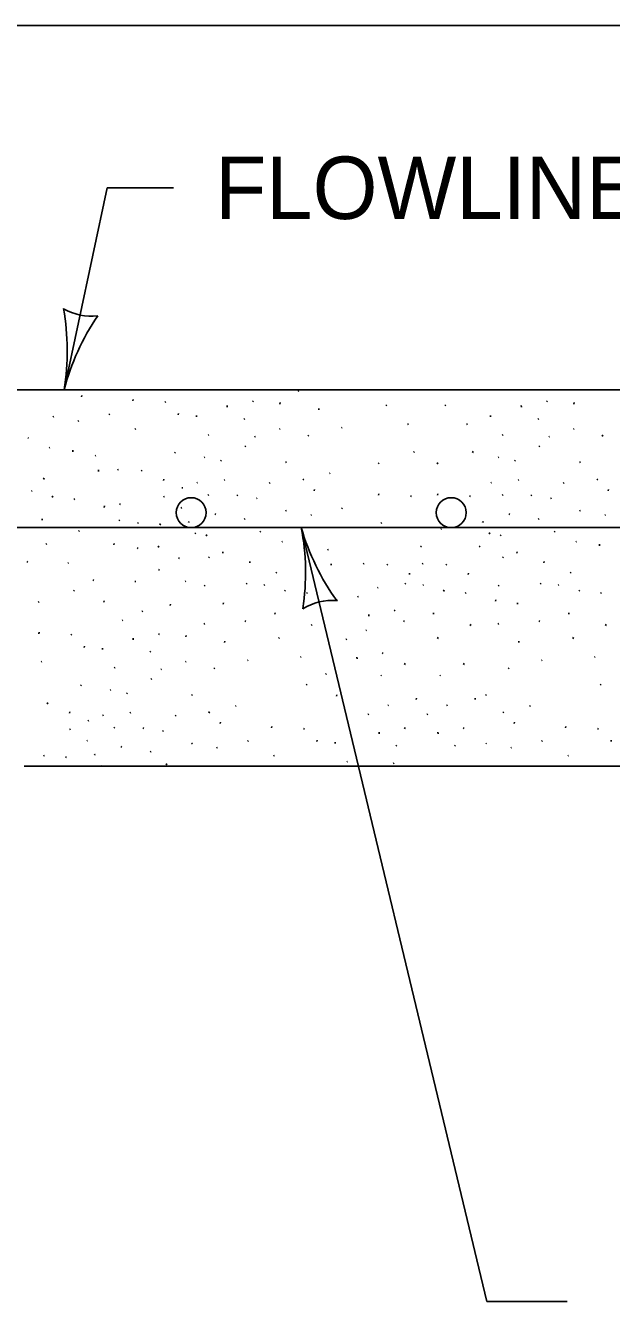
# Model space of a CAD drawing. Extents: x 49991.4 to 50029.7, y 49987.6 to 50011.4.
# Drawn here: x 50028.064 to 50028.627, y 49992.655 to 49993.881 of the extents above; entities that cross this region are included whole.
import ezdxf

# ---------------------------------------------------------------- set-up
doc = ezdxf.new("R2010")
doc.units = 0
for name, color, linetype in [('Level 1', 7, 'Continuous'), ('Level 2', 7, 'Continuous'), ('Level 3', 7, 'Continuous'), ('Level 4', 7, 'Continuous'), ('Level 5', 7, 'Continuous'), ('Level 9', 7, 'Continuous')]:
    doc.layers.add(name, color=color, linetype=linetype)

msp = doc.modelspace()

# ---------------------------------------------------------------- linework, layer by layer
at = {"layer": 'Level 1'}
for p, q in [((50028.0661, 49993.5314), (50029.3148, 49993.5314)), ((50028.0624, 49993.1696), (50029.3148, 49993.1696))]:
    msp.add_line(p, q, dxfattribs=at)
for centre in [(50028.223, 49993.4133), (50028.473, 49993.4133)]:
    msp.add_circle(centre, 0.0144, dxfattribs=at)
at = {"layer": 'Level 3'}
for p, q in [((50028.1421, 49993.7255), (50028.101, 49993.5314)), ((50028.1421, 49993.7255), (50028.2061, 49993.7255)), ((50028.3288, 49993.3989), (50028.5073, 49992.6553)), ((50028.5073, 49992.6553), (50028.5844, 49992.6553))]:
    msp.add_line(p, q, dxfattribs=at)
for centre, radius, start, end in [((50028.1276, 49993.6568), 0.0548, 240.156, 275.8784), ((50027.8709, 49993.5685), 0.233, 350.8445, 10.0944), ((50028.3163, 49993.4763), 0.2223, 145.4732, 165.6567), ((50028.1107, 49993.356), 0.2223, 350.9492, 11.1327), ((50028.5524, 49993.4644), 0.233, 196.3205, 215.5704), ((50028.3588, 49993.2742), 0.0548, 85.632, 121.3544)]:
    msp.add_arc(centre, radius, start, end, dxfattribs=at)
at = {"layer": 'Level 4'}
msp.add_line((50027.9165, 49993.3989), (50029.0416, 49993.3989), dxfattribs=at)
at = {"layer": 'Level 5'}
for p, q in [((50029.3148, 49993.8814), (50026.0794, 49993.8814)), ((50028.0661, 49993.5314), (50027.8717, 49993.5314))]:
    msp.add_line(p, q, dxfattribs=at)
at = {"layer": 'Level 9'}
for p, q in [((50028.3264, 49993.5303), (50028.3256, 49993.5299)), ((50028.1178, 49993.526), (50028.1176, 49993.5247)), ((50028.1671, 49993.5219), (50028.1669, 49993.5206)), ((50028.1986, 49993.5191), (50028.1976, 49993.52)), ((50028.2829, 49993.5198), (50028.2819, 49993.5206)), ((50028.3085, 49993.519), (50028.3082, 49993.5177)), ((50028.5656, 49993.5198), (50028.5646, 49993.5206)), ((50028.5911, 49993.519), (50028.5909, 49993.5177)), ((50028.0909, 49993.5057), (50028.0901, 49993.5053)), ((50028.1448, 49993.5074), (50028.1438, 49993.5083)), ((50028.2108, 49993.5086), (50028.2106, 49993.5073)), ((50028.2282, 49993.5066), (50028.228, 49993.5053)), ((50028.2576, 49993.5162), (50028.2577, 49993.5148)), ((50028.3458, 49993.5134), (50028.3456, 49993.5121)), ((50028.411, 49993.516), (50028.41, 49993.5168)), ((50028.4677, 49993.516), (50028.4667, 49993.5168)), ((50028.5109, 49993.5066), (50028.5107, 49993.5053)), ((50028.5403, 49993.5162), (50028.5404, 49993.5148)), ((50028.115, 49993.5016), (50028.1142, 49993.5012)), ((50028.1698, 49993.494), (50028.169, 49993.4936)), ((50028.2746, 49993.5029), (50028.2736, 49993.5038)), ((50028.3086, 49993.494), (50028.3078, 49993.4936)), ((50028.3682, 49993.4951), (50028.3674, 49993.4948)), ((50028.4319, 49993.4985), (50028.4311, 49993.4981)), ((50028.4886, 49993.4985), (50028.4877, 49993.4981)), ((50028.5573, 49993.5029), (50028.5563, 49993.5038)), ((50028.5913, 49993.494), (50028.5905, 49993.4936)), ((50028.0665, 49993.4849), (50028.0661, 49993.4852)), ((50028.2401, 49993.4881), (50028.2393, 49993.4877)), ((50028.2848, 49993.4866), (50028.284, 49993.4862)), ((50028.3362, 49993.4868), (50028.3352, 49993.4877)), ((50028.5228, 49993.4881), (50028.522, 49993.4877)), ((50028.5675, 49993.4866), (50028.5667, 49993.4862)), ((50028.6189, 49993.4868), (50028.6179, 49993.4877)), ((50028.0872, 49993.476), (50028.0864, 49993.4757)), ((50028.1091, 49993.4733), (50028.1092, 49993.4719)), ((50028.2079, 49993.4706), (50028.2069, 49993.4715)), ((50028.2755, 49993.4767), (50028.2745, 49993.4776)), ((50028.4376, 49993.4712), (50028.4366, 49993.4721)), ((50028.4943, 49993.4712), (50028.4932, 49993.4721)), ((50028.5582, 49993.4767), (50028.5572, 49993.4776)), ((50028.1314, 49993.4683), (50028.1306, 49993.468)), ((50028.2362, 49993.4666), (50028.2354, 49993.4663)), ((50028.2521, 49993.4629), (50028.2511, 49993.4637)), ((50028.3145, 49993.462), (50028.3137, 49993.4616)), ((50028.4037, 49993.4603), (50028.4027, 49993.4612)), ((50028.4603, 49993.4603), (50028.4593, 49993.4612)), ((50028.5189, 49993.4666), (50028.518, 49993.4663)), ((50028.5348, 49993.4629), (50028.5338, 49993.4637)), ((50028.5972, 49993.462), (50028.5964, 49993.4616)), ((50028.0819, 49993.4455), (50028.0808, 49993.4464)), ((50028.1339, 49993.4544), (50028.134, 49993.453)), ((50028.153, 49993.4548), (50028.1522, 49993.4545)), ((50028.1758, 49993.4533), (50028.1748, 49993.4542)), ((50028.1967, 49993.4456), (50028.1965, 49993.4443)), ((50028.2554, 49993.4449), (50028.2546, 49993.4445)), ((50028.3312, 49993.4448), (50028.3302, 49993.4456)), ((50028.3567, 49993.4512), (50028.3559, 49993.4509)), ((50028.5381, 49993.4449), (50028.5373, 49993.4445)), ((50028.6139, 49993.4448), (50028.6129, 49993.4456)), ((50028.0702, 49993.4342), (50028.0694, 49993.4338)), ((50028.2149, 49993.4373), (50028.214, 49993.437)), ((50028.2291, 49993.4424), (50028.2283, 49993.442)), ((50028.299, 49993.4414), (50028.298, 49993.4422)), ((50028.3415, 49993.4357), (50028.3412, 49993.4344)), ((50028.5118, 49993.4424), (50028.511, 49993.442)), ((50028.5817, 49993.4414), (50028.5807, 49993.4422)), ((50028.6242, 49993.4357), (50028.6239, 49993.4344)), ((50028.0902, 49993.4283), (50028.0892, 49993.4291)), ((50028.1111, 49993.4265), (50028.1103, 49993.4261)), ((50028.155, 49993.421), (50028.154, 49993.4219)), ((50028.1973, 49993.4288), (50028.1964, 49993.4285)), ((50028.2401, 49993.4299), (50028.2391, 49993.4308)), ((50028.2678, 49993.4294), (50028.2668, 49993.4303)), ((50028.2866, 49993.4272), (50028.2858, 49993.4269)), ((50028.4034, 49993.4315), (50028.4032, 49993.4302)), ((50028.4349, 49993.4288), (50028.4339, 49993.4296)), ((50028.4601, 49993.4315), (50028.4599, 49993.4302)), ((50028.4916, 49993.4288), (50028.4906, 49993.4296)), ((50028.5228, 49993.4299), (50028.5218, 49993.4308)), ((50028.5504, 49993.4294), (50028.5494, 49993.4303)), ((50028.5693, 49993.4272), (50028.5685, 49993.4269)), ((50028.1397, 49993.4197), (50028.1394, 49993.4184)), ((50028.2139, 49993.4181), (50028.213, 49993.4177)), ((50028.2467, 49993.4115), (50028.2457, 49993.4123)), ((50028.3145, 49993.4153), (50028.3137, 49993.415)), ((50028.3387, 49993.4112), (50028.3379, 49993.4109)), ((50028.3684, 49993.4171), (50028.3674, 49993.418)), ((50028.5294, 49993.4115), (50028.5284, 49993.4123)), ((50028.5972, 49993.4153), (50028.5964, 49993.415)), ((50028.6214, 49993.4112), (50028.6205, 49993.4109)), ((50028.0799, 49993.4073), (50028.0797, 49993.406)), ((50028.1158, 49993.3952), (50028.1148, 49993.3961)), ((50028.1545, 49993.4054), (50028.1535, 49993.4063)), ((50028.1723, 49993.4036), (50028.1715, 49993.4033)), ((50028.1937, 49993.4016), (50028.1927, 49993.4025)), ((50028.2204, 49993.404), (50028.2208, 49993.4044)), ((50028.2208, 49993.4044), (50028.2212, 49993.4045)), ((50028.2749, 49993.4074), (50028.274, 49993.407)), ((50028.2901, 49993.3945), (50028.2891, 49993.3954)), ((50028.4062, 49993.4036), (50028.4053, 49993.4033)), ((50028.4628, 49993.4036), (50028.462, 49993.4033)), ((50028.4637, 49993.3977), (50028.4629, 49993.3974)), ((50028.5031, 49993.404), (50028.5035, 49993.4044)), ((50028.5035, 49993.4044), (50028.5039, 49993.4045)), ((50028.5575, 49993.4074), (50028.5567, 49993.407)), ((50028.5728, 49993.3945), (50028.5718, 49993.3954)), ((50028.0844, 49993.3827), (50028.0834, 49993.3836)), ((50028.149, 49993.3838), (50028.1488, 49993.3825)), ((50028.2276, 49993.3929), (50028.2266, 49993.3938)), ((50028.2383, 49993.3911), (50028.2372, 49993.392)), ((50028.3108, 49993.3857), (50028.31, 49993.3853)), ((50028.5103, 49993.3929), (50028.5093, 49993.3938)), ((50028.5209, 49993.3911), (50028.5199, 49993.392)), ((50028.5935, 49993.3857), (50028.5927, 49993.3853)), ((50028.1721, 49993.3788), (50028.1711, 49993.3796)), ((50028.1921, 49993.3801), (50028.1911, 49993.381)), ((50028.2406, 49993.37), (50028.2396, 49993.3709)), ((50028.2536, 49993.3756), (50028.2534, 49993.3743)), ((50028.3327, 49993.3829), (50028.3328, 49993.3815)), ((50028.355, 49993.378), (50028.3542, 49993.3776)), ((50028.4443, 49993.3803), (50028.4433, 49993.3811)), ((50028.5009, 49993.3803), (50028.4999, 49993.3811)), ((50028.5233, 49993.37), (50028.5223, 49993.3709)), ((50028.5363, 49993.3756), (50028.5361, 49993.3743)), ((50028.6154, 49993.3829), (50028.6155, 49993.3815)), ((50028.0659, 49993.3656), (50028.0649, 49993.3664)), ((50028.1052, 49993.3652), (50028.1044, 49993.3649)), ((50028.1926, 49993.3579), (50028.1916, 49993.3587)), ((50028.2117, 49993.3691), (50028.2107, 49993.3699)), ((50028.2795, 49993.3664), (50028.2793, 49993.3651)), ((50028.3576, 49993.3641), (50028.3577, 49993.3627)), ((50028.3894, 49993.3645), (50028.3885, 49993.3641)), ((50028.4121, 49993.363), (50028.4111, 49993.3638)), ((50028.446, 49993.3645), (50028.4452, 49993.3641)), ((50028.4688, 49993.363), (50028.4678, 49993.3638)), ((50028.5622, 49993.3664), (50028.562, 49993.3651)), ((50028.1295, 49993.3481), (50028.1285, 49993.3489)), ((50028.1697, 49993.3473), (50028.1689, 49993.347)), ((50028.2179, 49993.3474), (50028.2171, 49993.3471)), ((50028.3055, 49993.3552), (50028.3045, 49993.356)), ((50028.433, 49993.3553), (50028.4328, 49993.354)), ((50028.4897, 49993.3553), (50028.4894, 49993.354)), ((50028.5882, 49993.3552), (50028.5872, 49993.356)), ((50028.1109, 49993.3379), (50028.1099, 49993.3388)), ((50028.2365, 49993.3427), (50028.2355, 49993.3435)), ((50028.2769, 49993.3446), (50028.2759, 49993.3455)), ((50028.2938, 49993.3438), (50028.293, 49993.3435)), ((50028.3138, 49993.3379), (50028.3128, 49993.3388)), ((50028.3347, 49993.3361), (50028.3339, 49993.3358)), ((50028.4028, 49993.3414), (50028.402, 49993.341)), ((50028.4295, 49993.3446), (50028.4285, 49993.3455)), ((50028.4464, 49993.3438), (50028.4456, 49993.3435)), ((50028.4664, 49993.3379), (50028.4654, 49993.3388)), ((50028.4873, 49993.3361), (50028.4865, 49993.3358)), ((50028.5192, 49993.3427), (50028.5182, 49993.3435)), ((50028.5596, 49993.3446), (50028.5586, 49993.3455)), ((50028.5765, 49993.3438), (50028.5757, 49993.3435)), ((50028.5965, 49993.3379), (50028.5955, 49993.3388)), ((50028.6174, 49993.3361), (50028.6166, 49993.3358)), ((50028.077, 49993.3271), (50028.076, 49993.3279)), ((50028.1393, 49993.3285), (50028.1391, 49993.3272)), ((50028.2032, 49993.3254), (50028.2029, 49993.3241)), ((50028.2541, 49993.3268), (50028.2539, 49993.3255)), ((50028.3633, 49993.3294), (50028.3631, 49993.3281)), ((50028.3838, 49993.3328), (50028.383, 49993.3324)), ((50028.5159, 49993.3294), (50028.5156, 49993.3281)), ((50028.5368, 49993.3268), (50028.5366, 49993.3255)), ((50028.1574, 49993.3101), (50028.1566, 49993.3098)), ((50028.1764, 49993.3187), (50028.1756, 49993.3184)), ((50028.2756, 49993.3086), (50028.2745, 49993.3095)), ((50028.3036, 49993.317), (50028.3033, 49993.3156)), ((50028.3937, 49993.3153), (50028.3938, 49993.3139)), ((50028.419, 49993.3188), (50028.418, 49993.3196)), ((50028.4281, 49993.3086), (50028.4271, 49993.3095)), ((50028.4561, 49993.317), (50028.4559, 49993.3156)), ((50028.5582, 49993.3086), (50028.5572, 49993.3095)), ((50028.5862, 49993.317), (50028.586, 49993.3156)), ((50028.0768, 49993.2983), (50028.0765, 49993.297)), ((50028.236, 49993.3067), (50028.2352, 49993.3063)), ((50028.3394, 49993.3048), (50028.3384, 49993.3057)), ((50028.3916, 49993.3004), (50028.3908, 49993.3)), ((50028.492, 49993.3048), (50028.491, 49993.3057)), ((50028.5187, 49993.3067), (50028.5179, 49993.3063)), ((50028.6221, 49993.3048), (50028.6211, 49993.3057)), ((50028.1082, 49993.2955), (50028.1072, 49993.2964)), ((50028.1205, 49993.285), (50028.1202, 49993.2837)), ((50028.1672, 49993.2926), (50028.1673, 49993.2912)), ((50028.1925, 49993.2961), (50028.1915, 49993.297)), ((50028.2181, 49993.2954), (50028.2179, 49993.2941)), ((50028.2554, 49993.2897), (50028.2552, 49993.2884)), ((50028.308, 49993.2923), (50028.307, 49993.2932)), ((50028.3726, 49993.2918), (50028.3718, 49993.2915)), ((50028.4606, 49993.2923), (50028.4596, 49993.2932)), ((50028.5381, 49993.2897), (50028.5379, 49993.2884)), ((50028.5907, 49993.2923), (50028.5897, 49993.2932)), ((50028.1379, 49993.283), (50028.1377, 49993.2817)), ((50028.1843, 49993.2793), (50028.1833, 49993.2802)), ((50028.3289, 49993.2748), (50028.328, 49993.2745)), ((50028.3824, 49993.2743), (50028.3825, 49993.2729)), ((50028.4077, 49993.2778), (50028.4067, 49993.2787)), ((50028.6115, 49993.2748), (50028.6107, 49993.2745)), ((50028.0795, 49993.2703), (50028.0787, 49993.27)), ((50028.1498, 49993.2644), (50028.1489, 49993.2641)), ((50028.1945, 49993.2629), (50028.1937, 49993.2626)), ((50028.2182, 49993.2704), (50028.2174, 49993.27)), ((50028.2459, 49993.2632), (50028.2449, 49993.2641)), ((50028.2778, 49993.2715), (50028.277, 49993.2712)), ((50028.4289, 49993.2675), (50028.4279, 49993.2684)), ((50028.4856, 49993.2675), (50028.4845, 49993.2684)), ((50028.5286, 49993.2632), (50028.5276, 49993.2641)), ((50028.5605, 49993.2715), (50028.5597, 49993.2712)), ((50028.1852, 49993.2531), (50028.1842, 49993.2539)), ((50028.3345, 49993.2476), (50028.3335, 49993.2484)), ((50028.3531, 49993.2577), (50028.3521, 49993.2586)), ((50028.4061, 49993.257), (50028.4052, 49993.2566)), ((50028.4627, 49993.257), (50028.4619, 49993.2566)), ((50028.6172, 49993.2476), (50028.6162, 49993.2484)), ((50028.1176, 49993.247), (50028.1166, 49993.2478)), ((50028.1458, 49993.243), (50028.145, 49993.2427)), ((50028.1618, 49993.2392), (50028.1608, 49993.2401)), ((50028.2242, 49993.2383), (50028.2233, 49993.238)), ((50028.3629, 49993.2381), (50028.3627, 49993.2368)), ((50028.5069, 49993.2383), (50028.506, 49993.238)), ((50028.0854, 49993.2297), (50028.0844, 49993.2306)), ((50028.2664, 49993.2276), (50028.2655, 49993.2273)), ((50028.4127, 49993.2284), (50028.4119, 49993.228)), ((50028.4395, 49993.235), (50028.4393, 49993.2337)), ((50028.4694, 49993.2284), (50028.4686, 49993.228)), ((50028.4961, 49993.235), (50028.4959, 49993.2337)), ((50028.5491, 49993.2276), (50028.5482, 49993.2273)), ((50028.1063, 49993.222), (50028.1061, 49993.2207)), ((50028.1245, 49993.2137), (50028.1237, 49993.2133)), ((50028.1387, 49993.2188), (50028.1379, 49993.2184)), ((50028.1651, 49993.2213), (50028.1642, 49993.2209)), ((50028.2087, 49993.2177), (50028.2077, 49993.2186)), ((50028.2408, 49993.2211), (50028.2398, 49993.222)), ((50028.2511, 49993.2121), (50028.2509, 49993.2108)), ((50028.3937, 49993.2198), (50028.3929, 49993.2194)), ((50028.4504, 49993.2198), (50028.4496, 49993.2194)), ((50028.5235, 49993.2211), (50028.5225, 49993.222)), ((50028.5338, 49993.2121), (50028.5336, 49993.2108)), ((50028.1069, 49993.2052), (50028.1061, 49993.2049)), ((50028.1497, 49993.2063), (50028.1487, 49993.2071)), ((50028.1774, 49993.2058), (50028.1764, 49993.2066)), ((50028.1963, 49993.2036), (50028.1955, 49993.2032)), ((50028.3004, 49993.2079), (50028.3002, 49993.2066)), ((50028.3319, 49993.2052), (50028.3309, 49993.206)), ((50028.4036, 49993.2023), (50028.4037, 49993.2009)), ((50028.4289, 49993.2058), (50028.4279, 49993.2066)), ((50028.4602, 49993.2023), (50028.4603, 49993.2009)), ((50028.4855, 49993.2058), (50028.4845, 49993.2066)), ((50028.5831, 49993.2079), (50028.5828, 49993.2066)), ((50028.6146, 49993.2052), (50028.6136, 49993.206)), ((50028.1235, 49993.1944), (50028.1227, 49993.1941)), ((50028.1563, 49993.1878), (50028.1553, 49993.1887)), ((50028.2242, 49993.1917), (50028.2234, 49993.1913)), ((50028.2483, 49993.1876), (50028.2475, 49993.1873)), ((50028.2781, 49993.1935), (50028.2771, 49993.1943)), ((50028.3441, 49993.1947), (50028.3439, 49993.1934)), ((50028.3615, 49993.1927), (50028.3613, 49993.1914)), ((50028.4206, 49993.189), (50028.4196, 49993.1898)), ((50028.4772, 49993.189), (50028.4762, 49993.1898)), ((50028.5069, 49993.1917), (50028.5061, 49993.1913)), ((50028.531, 49993.1876), (50028.5302, 49993.1873)), ((50028.5608, 49993.1935), (50028.5598, 49993.1943)), ((50028.6268, 49993.1947), (50028.6266, 49993.1934)), ((50028.082, 49993.18), (50028.0812, 49993.1797)), ((50028.1033, 49993.178), (50028.1023, 49993.1788)), ((50028.13, 49993.1804), (50028.1305, 49993.1808)), ((50028.1305, 49993.1808), (50028.1308, 49993.1809)), ((50028.1845, 49993.1838), (50028.1837, 49993.1834)), ((50028.3031, 49993.18), (50028.3023, 49993.1796)), ((50028.5858, 49993.18), (50028.585, 49993.1796)), ((50028.1369, 49993.1696), (50028.1363, 49993.1701)), ((50028.1998, 49993.1709), (50028.1988, 49993.1718)), ((50028.3734, 49993.1741), (50028.3726, 49993.1737)), ((50028.4181, 49993.1726), (50028.4173, 49993.1722))]:
    msp.add_line(p, q, dxfattribs=at)

# ---------------------------------------------------------------- texts
at = {"layer": 'Level 2'}
msp.add_text('FLOWLINE', height=0.06, dxfattribs=at).set_placement((50028.2461, 49993.6955))

doc.saveas('drawing.dxf')
